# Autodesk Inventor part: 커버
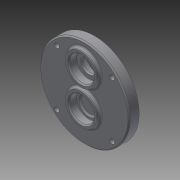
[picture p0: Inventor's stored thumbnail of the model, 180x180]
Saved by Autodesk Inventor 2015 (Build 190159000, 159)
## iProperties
Created: 2014-12
Part Number: 커버
Material: 일반
Document SubType Name: Modeling
Designer: 영환
Density: 1 g/cm^3
Appearance: 기본값
Author: 영환
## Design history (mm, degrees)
node "작업 평면1"
sketch "스케치1"
  geometry: C1 r 40 at (0, 0); 1 further point
  constraints: 1 centre point, 1 coincident
  dimensions: "d1" = 80 diameter of C1
extrude "돌출1" new body sketch "스케치1" distance "d2" = 9; taper "d3" = 0 deg
sketch "스케치2"
  geometry: 5 further points
  constraints: 5 other
  dimensions: "d4" = 35 distance of point (24.749, 24.749) point (0, 0); "d7" = 360 deg dimension on point (0, 0) point (24.749, 24.749) (derived)
hole "구멍1" sketch "스케치2" at (24.749, 24.749), (-24.749, 24.749), (-24.749, -24.749), (24.749, -24.749) diameter "d9" = 4.5; stored, may be unused: countersink angle "d13" = 90 deg, drill point angle "d15" = 118 deg; dims "d10" = 6, "d11" = 8, "d12" = 4.4, "d14" = 8
sketch "스케치3"
  geometry: C1 r 15 at (0, -20); 2 further points
  constraints: 1 centre point, 1 coincident, 1 vertical alignment
  dimensions: "d16" = 20 distance of point (0, 0) point (0, -20); "d17" = 30 diameter of C1
extrude "돌출2" join sketch "스케치3" distance "d18" = 4; taper "d19" = 0 deg
hole "구멍2" diameter "d22" = 15; stored, may be unused: countersink angle "d26" = 90 deg, drill point angle "d28" = 118 deg; dims "d20" = 10, "d21" = 10, "d23" = 6, "d24" = 22, "d25" = 7, "d27" = 8
sketch "스케치4"
  geometry: C1 r 7.5 at (0, 20) reference; C2 r 14 at (0, -11); C3 r 14 at (0, 20); 1 further point
  constraints: 2 centre point, 1 coincident, 1 vertical alignment
  dimensions: "d29" = 28 diameter of C2; "d30" = 11 distance of C2.centre point (0, 0); "d31" = 28 diameter of C3
extrude "돌출3" join sketch "스케치4" distance "d32" = 3; taper "d33" = 0 deg
hole "구멍3" diameter "d36" = 22; stored, may be unused: countersink angle "d40" = 90 deg, drill point angle "d42" = 0 deg; dims "d34" = 10, "d35" = 10, "d37" = 6, "d38" = 22, "d39" = 7, "d41" = 7
hole "구멍4" diameter "d45" = 18; stored, may be unused: countersink angle "d49" = 90 deg, drill point angle "d51" = 0 deg; dims "d43" = 10, "d44" = 10, "d46" = 6, "d47" = 22, "d48" = 7, "d50" = 8
chamfer "모따기1" distance "d52" = 1; stored, may be unused: second distance "d53" = 2, angle "d54" = 45 deg
fillet "모깎기1" dims "d55" = 0.3
fillet "모깎기2" dims "d56" = 2
chamfer "모따기2" distance "d57" = 1; stored, may be unused: second distance "d58" = 2, angle "d59" = 45 deg
fillet "모깎기3" dims "d60" = 2
node "솔리드1"
other parameters: "d0" = 3
